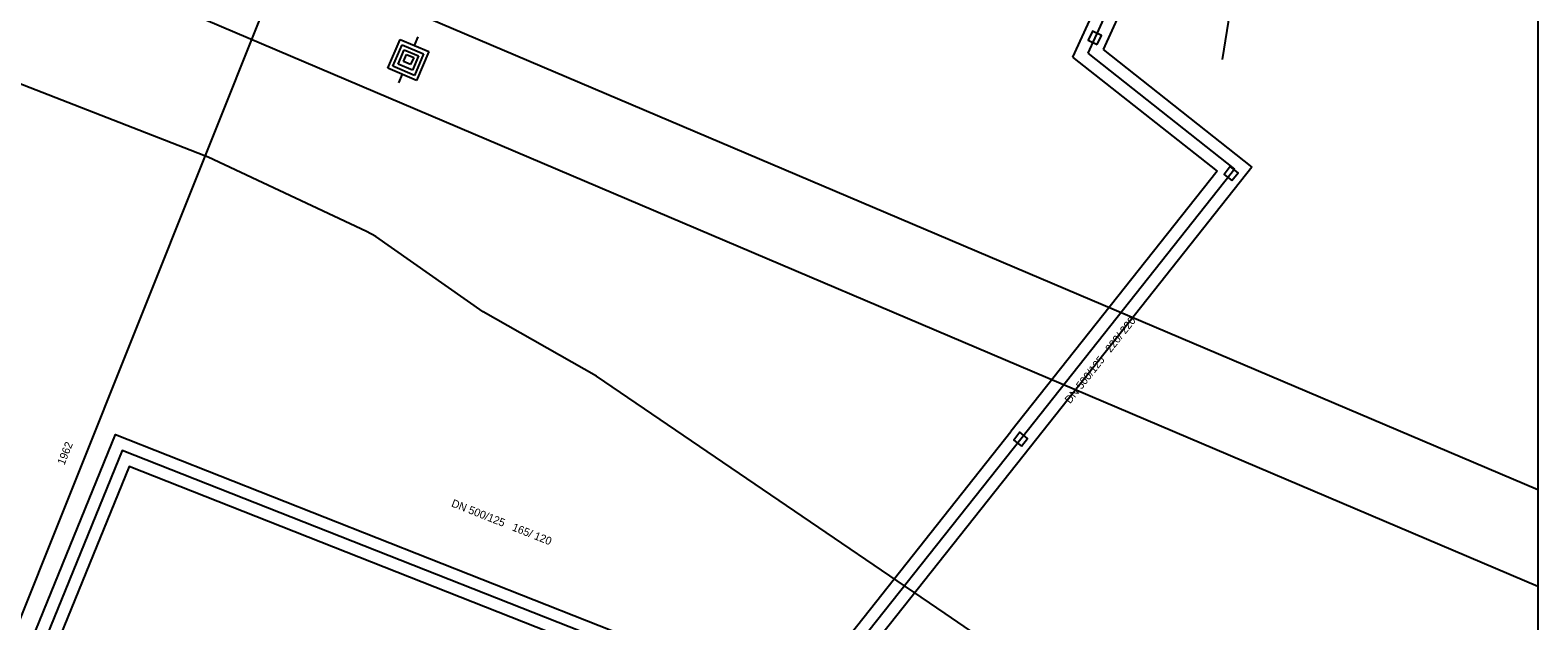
# Model space of a CAD drawing. Extents: x -596024 to -594475, y -1163820 to -1161957.
# Drawn here: x -594627.8 to -594475.5, y -1162134.9 to -1162075.2 of the extents above; entities that cross this region are included whole.
import ezdxf

# ---------------------------------------------------------------- set-up
doc = ezdxf.new("R2010")
doc.units = 0
for name, color, linetype in [('Level 1', 7, 'Continuous'), ('Vrstva 13', 7, 'Continuous'), ('Vrstva 15', 7, 'Continuous'), ('Vrstva 22', 7, 'Continuous'), ('Vrstva 29', 7, 'Continuous'), ('Vrstva 30', 7, 'Continuous'), ('Vrstva 31', 7, 'Continuous'), ('Vrstva 32', 7, 'Continuous'), ('Vrstva 47', 7, 'Continuous'), ('Vrstva 53', 7, 'Continuous'), ('Vrstva 63', 7, 'Continuous')]:
    doc.layers.add(name, color=color, linetype=linetype)

# ---------------------------------------------------------------- blocks, each defined once
blk = doc.blocks.new('WN200')
at = {"layer": 'Vrstva 53'}
for points in [[(-6.299, 6.3), (6.299, 6.3)], [(-6.299, -6.3), (-6.299, 6.3)], [(0, 6.3), (0, 10.136)], [(6.299, 6.3), (6.299, -6.3)], [(-4.724, 4.625), (4.724, 4.625)], [(-4.724, -4.823), (-4.724, 4.625)], [(-3.149, 3.151), (3.149, 3.151)], [(-3.149, -3.151), (-3.149, 3.151)], [(-1.575, -1.378), (-1.575, 1.772)], [(-1.575, 1.772), (1.575, 1.772)], [(1.575, 1.772), (1.575, -1.378)], [(3.149, 3.151), (3.149, -3.151)], [(4.724, 4.625), (4.724, -4.823)], [(4.724, -4.823), (-4.724, -4.823)], [(3.149, -3.151), (-3.149, -3.151)], [(1.575, -1.378), (-1.575, -1.378)], [(6.299, -6.3), (-6.299, -6.3)], [(0, -6.3), (0, -10.136)]]:
    blk.add_lwpolyline(points, dxfattribs=at)

msp = doc.modelspace()

# ---------------------------------------------------------------- linework, layer by layer
at = {"layer": 'Level 1'}
msp.add_lwpolyline([(-594505.8, -1162068.48), (-594507.37, -1162078.16)], dxfattribs=at)
at = {"layer": 'Vrstva 13'}
msp.add_line((-594596.819, -1162054.54), (-594654.099, -1162197.927), dxfattribs=at)
at = {"layer": 'Vrstva 22'}
msp.add_lwpolyline([(-594476.87, -1162175.29), (-594509.12, -1162152.12), (-594535.35, -1162134.16), (-594570.58, -1162110.16), (-594582.03, -1162103.66), (-594592.86, -1162096.04), (-594593.83, -1162095.56), (-594609.83, -1162088.03), (-594610.25, -1162087.87), (-594659.88, -1162068.49), (-594665.28, -1162066.38), (-594698.94, -1162053.42), (-594746.09, -1162031.77), (-594763.28, -1162023.08), (-594810.88, -1161999.03), (-594853.79, -1161974.89), (-594885.054, -1161956.88)], dxfattribs=at)
at = {"layer": 'Vrstva 29'}
msp.add_line((-594520.942, -1162077.535), (-594506.113, -1162089.253), dxfattribs=at)
for points in [[(-594490.174, -1162010.23), (-594520.227, -1162075.971), (-594520.227, -1162075.971), (-594520.942, -1162077.535)], [(-594506.113, -1162089.253), (-594506.463, -1162089.695), (-594527.721, -1162116.547)], [(-594527.721, -1162116.547), (-594550.035, -1162144.733), (-594618.49, -1162117.698), (-594660.636, -1162221.142), (-594706.437, -1162202.481)]]:
    msp.add_lwpolyline(points, dxfattribs=at)
at = {"layer": 'Vrstva 30'}
for p, q in [((-594491.311, -1162009.71), (-594522.487, -1162077.908)), ((-594489.037, -1162010.75), (-594519.397, -1162077.162)), ((-594519.397, -1162077.162), (-594504.356, -1162089.048)), ((-594522.487, -1162077.908), (-594507.87, -1162089.458)), ((-594507.87, -1162089.458), (-594528.701, -1162115.771)), ((-594504.356, -1162089.048), (-594526.741, -1162117.323))]:
    msp.add_line(p, q, dxfattribs=at)
for points in [[(-594706.74, -1162201.008), (-594661.322, -1162219.513), (-594619.181, -1162116.081), (-594550.439, -1162143.229), (-594528.701, -1162115.771)], [(-594526.741, -1162117.323), (-594549.631, -1162146.237), (-594617.799, -1162119.315), (-594659.95, -1162222.771), (-594706.133, -1162203.955)]]:
    msp.add_lwpolyline(points, dxfattribs=at)
at = {"layer": 'Vrstva 31'}
for points in [[(-594519.981, -1162076.634), (-594519.565, -1162075.724), (-594520.475, -1162075.308), (-594520.891, -1162076.218)], [(-594506.381, -1162090.397), (-594505.761, -1162089.613), (-594506.545, -1162088.993), (-594507.165, -1162089.777)], [(-594527.639, -1162117.249), (-594527.019, -1162116.465), (-594527.803, -1162115.845), (-594528.423, -1162116.629)]]:
    msp.add_lwpolyline(points, close=True, dxfattribs=at)
at = {"layer": 'Vrstva 53'}
for p, q in [((-594475.47, -1162121.662), (-594743.26, -1162007.807)), ((-594747.926, -1162015.46), (-594475.47, -1162131.403))]:
    msp.add_line(p, q, dxfattribs=at)
at = {"layer": 'Vrstva 63'}
msp.add_lwpolyline([(-594475.47, -1163820.23), (-596024.42, -1163820.23), (-596024.42, -1161956.88), (-594475.47, -1161956.88)], close=True, dxfattribs=at)

# ---------------------------------------------------------------- block references
at = {"layer": 'Vrstva 47', "xscale": 0.25, "yscale": 0.25, "rotation": -23.00000000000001}
msp.add_blockref('WN200', (-594589.586, -1162078.201), dxfattribs=at)

# ---------------------------------------------------------------- texts
at = {"layer": 'Vrstva 15'}
msp.add_text('1962', height=0.8, rotation=68.29657, dxfattribs=at).set_placement((-594624.346, -1162119.222))
at = {"layer": 'Vrstva 32'}
for s, rotation, p in [('DN 500/125   220/ 220', 51.6235, (-594522.724, -1162113.015)), ('DN 500/125   165/ 120', 338.44617, (-594585.314, -1162123.327))]:
    msp.add_text(s, height=0.8, rotation=rotation, dxfattribs=at).set_placement(p)

doc.saveas('drawing.dxf')
